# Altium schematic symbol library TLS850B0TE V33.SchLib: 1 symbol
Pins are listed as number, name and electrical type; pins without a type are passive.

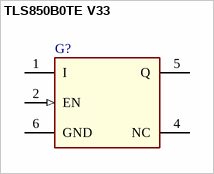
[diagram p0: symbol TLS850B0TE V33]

## TLS850B0TE V33
designator G?  (value not drawn)
Low dropout linear voltage regulator, Fixed output voltage 3.3 V, Output voltage accuracy ≤ ±2%; Manufacturer: Infineon Technologies
footprint TO114P998X250-6_5N-1
pins: 1 I (power) "Input", 2 EN (in) "Enable", 4 NC "Not Connected", 5 Q (power) "Output", 6 GND (power) "Heat Slug"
